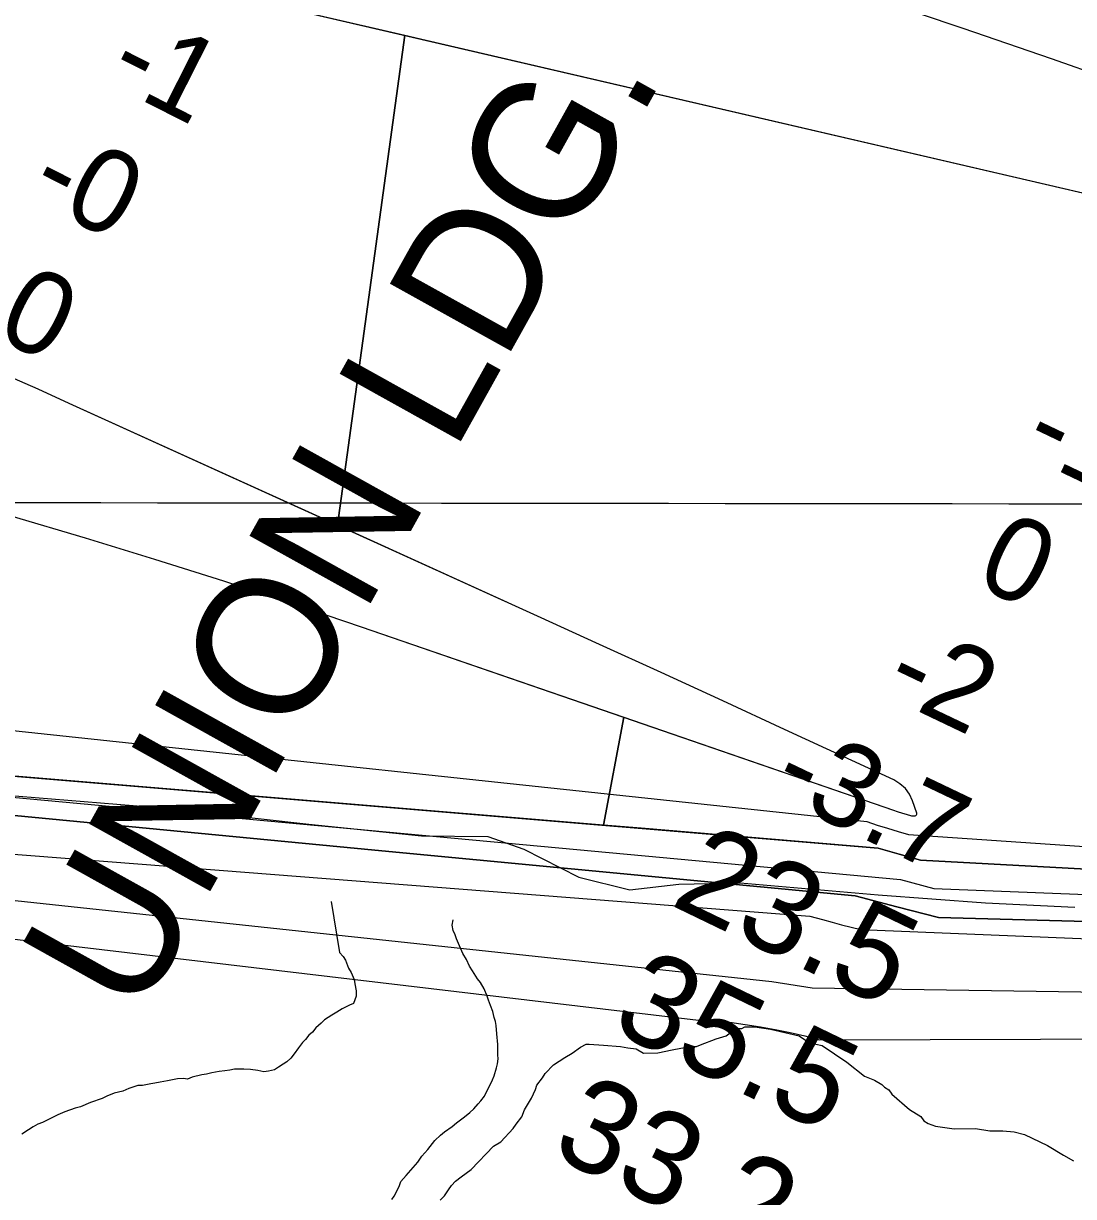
# Model space of a CAD drawing. Extents: x 3219052 to 3256913, y 800770 to 826146.
# Drawn here: x 3237861 to 3238618, y 811725 to 812571 of the extents above; entities that cross this region are included whole.
import ezdxf

# ---------------------------------------------------------------- set-up
doc = ezdxf.new("R2010")
doc.units = 0
for name, color, linetype in [('V-GRID-MAJR', 7, 'Continuous'), ('V-RIVR-EDGE', 7, 'Continuous'), ('V-RIVR-RANG', 7, 'Continuous'), ('V-SITE-VEGE', 7, 'Continuous'), ('V-TOPO-DPTH', 7, 'Continuous'), ('V-TOPO-GNAM-IDEN', 7, 'Continuous'), ('V-TOPO-MAJR', 7, 'Continuous'), ('V-TOPO-MINR', 7, 'Continuous'), ('V-TOPO-SHOR', 7, 'Continuous'), ('V-TOPO-WATR', 7, 'Continuous')]:
    doc.layers.add(name, color=color, linetype=linetype)

msp = doc.modelspace()

# ---------------------------------------------------------------- linework, layer by layer
at = {"layer": 'V-GRID-MAJR'}
msp.add_spline([(3223229.222, 812245.659), (3228465.955, 812237.661), (3233702.6890000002, 812230.425), (3238939.4250000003, 812223.951), (3244176.161, 812218.238), (3249412.899, 812213.287), (3254649.637, 812209.098), (3254649.6380000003, 812209.098)], degree=3, dxfattribs=at)
at = {"layer": 'V-RIVR-EDGE'}
msp.add_lwpolyline([(3237845.700200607, 812014.2978782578), (3237963.4749681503, 812004.8783922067), (3238066.465359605, 811993.322067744), (3238147.7294484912, 811984.8622204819), (3238195.5427916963, 811984.3093126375), (3238221.6008119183, 811975.1166157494), (3238261.106933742, 811955.0236859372), (3238298.031867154, 811945.804118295), (3238333.25141419, 811950.0638223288), (3238377.5905696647, 811950.8235427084), (3238477.1110727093, 811942.3185525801), (3238554.469521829, 811936.4764379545), (3238618.794124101, 811933.2746273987)], dxfattribs=at)
at = {"layer": 'V-SITE-VEGE'}
for points in [[(3238360.298, 811838.404), (3238367.481, 811840.603), (3238371.546, 811843.778), (3238375.634, 811845.9180000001), (3238378.728, 811845.9770000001), (3238380.772, 811847.046), (3238387.992, 811847.186), (3238399.376, 811845.336), (3238420.102, 811840.573), (3238427.424, 811835.5530000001), (3238436.7460000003, 811833.669), (3238454.515, 811821.623), (3238467.089, 811811.542), (3238474.3680000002, 811808.585), (3238479.5840000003, 811805.589), (3238481.688, 811803.5650000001), (3238484.821, 811801.56), (3238486.943, 811798.507), (3238499.536, 811787.394), (3238507.886, 811782.393), (3238510.007, 811779.34), (3238513.1410000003, 811777.335), (3238518.339, 811775.37), (3238531.786, 811773.562), (3238547.256, 811773.857), (3238557.611, 811771.9890000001), (3238566.895, 811772.165), (3238575.166, 811771.291), (3238582.427, 811769.366), (3238599.085, 811761.4280000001), (3238610.5700000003, 811754.424), (3238617.867, 811750.434)], [(3238161.3000000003, 811722.149), (3238164.336, 811725.3030000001), (3238167.352, 811729.487), (3238169.355, 811732.621), (3238172.392, 811735.774), (3238176.46, 811738.947), (3238183.5810000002, 811744.243), (3238199.77, 811761.059), (3238204.87, 811764.252), (3238213.975, 811773.712), (3238215.98, 811776.845), (3238220.008, 811782.082), (3238221.972, 811787.278), (3238226.974, 811795.627), (3238229.949, 811801.876), (3238230.92, 811804.9890000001), (3238234.951, 811810.223), (3238236.954, 811813.361), (3238243.026, 811819.665), (3238251.179, 811824.979), (3238256.279, 811828.172), (3238262.3880000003, 811832.4130000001), (3238266.4760000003, 811834.556), (3238268.538, 811834.595), (3238278.872, 811833.761), (3238291.269, 811832.964), (3238296.446, 811832.03), (3238302.6550000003, 811831.117), (3238307.872, 811828.1190000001), (3238318.185, 811828.3150000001), (3238328.46, 811830.574), (3238334.631, 811831.723), (3238341.832, 811832.8910000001), (3238345.9560000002, 811832.973), (3238349.032, 811834.062), (3238360.298, 811838.404)]]:
    msp.add_lwpolyline(points, dxfattribs=at)
at = {"layer": 'V-TOPO-DPTH'}
for points in [[(3238681.181071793, 812517.4234874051), (3238601.907386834, 812545.1668010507), (3238538.268799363, 812567.1180725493), (3238474.5027999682, 812588.6870187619), (3238410.545682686, 812609.6824770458), (3238346.4611534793, 812630.295610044), (3238054.0245241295, 812722.9125502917), (3238053.059886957, 812723.0832592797), (3238051.1972660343, 812722.8624435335), (3238048.5419894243, 812721.4004480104), (3238048.264964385, 812721.162598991), (3238048.1245901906, 812721.0453539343), (3237968.7772840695, 812656.8193267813), (3237966.404750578, 812654.3878513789), (3237964.6618460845, 812651.4718143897), (3237964.085610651, 812648.3539511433), (3237965.0067713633, 812645.3200458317), (3237977.105712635, 812624.8371600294), (3237984.90913081, 812614.0776569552), (3237993.786760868, 812604.5197553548), (3238004.2757087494, 812596.7642559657), (3238015.8388685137, 812590.2103580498), (3238800.1439429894, 812407.8218294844)], [(3238681.181071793, 812517.4234874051), (3238601.907386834, 812545.1668010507), (3238538.268799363, 812567.1180725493), (3238474.5027999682, 812588.6870187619), (3238410.545682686, 812609.6824770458), (3238346.4611534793, 812630.295610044), (3238054.0245241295, 812722.9125502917), (3238053.059886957, 812723.0832592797), (3238051.1972660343, 812722.8624435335), (3238048.5419894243, 812721.4004480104), (3238048.264964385, 812721.162598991), (3238048.1245901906, 812721.0453539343), (3237968.7772840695, 812656.8193267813), (3237966.404750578, 812654.3878513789), (3237964.6618460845, 812651.4718143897), (3237964.085610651, 812648.3539511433), (3237965.0067713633, 812645.3200458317), (3237977.105712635, 812624.8371600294), (3237984.90913081, 812614.0776569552), (3237993.786760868, 812604.5197553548), (3238004.2757087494, 812596.7642559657), (3238015.8388685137, 812590.2103580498), (3238135.8415661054, 812562.3039780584), (3238087.088944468, 812208.8483856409)], [(3238320.5143739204, 812102.5461848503), (3238275.991739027, 812122.9051701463), (3238231.4442780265, 812143.2099945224), (3238103.1016457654, 812201.5674080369), (3238087.088944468, 812208.8483856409), (3238135.8415661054, 812562.3039780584), (3238151.082310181, 812558.7597744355)], [(3238151.082310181, 812558.7597744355), (3238800.1439429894, 812407.8218294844), (3238805.0494680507, 812407.4696608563), (3238809.8531523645, 812407.7521796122)], [(3238320.5143739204, 812102.5461848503), (3238275.991739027, 812122.9051701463), (3238231.4442780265, 812143.2099945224), (3237893.7614052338, 812296.7544457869), (3237871.2860702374, 812306.889872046), (3237848.769443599, 812316.9319345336)], [(3238087.088944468, 812208.8483856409), (3237893.7614052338, 812296.7544457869), (3237871.2860702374, 812306.889872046), (3237848.769443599, 812316.9319345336)], [(3237851.6740228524, 812215.6477515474), (3237905.268645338, 812199.6485995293), (3237955.2658458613, 812184.378960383), (3238005.1283607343, 812168.6905035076), (3238054.7888471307, 812152.3738200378), (3238104.3146478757, 812135.6383188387), (3238487.9833535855, 812003.2866509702), (3238490.6115121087, 812002.4256119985), (3238491.4929302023, 812002.1552417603), (3238500.259794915, 811999.52442819), (3238501.101298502, 811999.3271251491), (3238503.6690818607, 811999.2202945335), (3238504.274176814, 811999.4867889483), (3238504.7023597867, 811999.8660077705), (3238504.865174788, 812000.4143132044), (3238504.851077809, 812001.0753430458), (3238501.874597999, 812009.9799408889), (3238499.5668234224, 812014.7749039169), (3238496.629291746, 812019.0059783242), (3238492.747124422, 812022.3912197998), (3238488.2351999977, 812025.2125726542), (3238409.4603392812, 812061.6115705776), (3238364.999769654, 812082.1059581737), (3238320.5143739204, 812102.5461848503)], [(3237851.6740228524, 812215.6477515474), (3237905.268645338, 812199.6485995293), (3237955.2658458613, 812184.378960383), (3238005.1283607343, 812168.6905035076), (3238054.7888471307, 812152.3738200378), (3238104.3146478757, 812135.6383188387), (3238293.5981568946, 812070.3424327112), (3238279.0662157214, 811992.5104605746)], [(3238279.0662157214, 811992.5104605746), (3236263.3109329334, 812160.2666766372)], [(3236263.3109329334, 812160.2666766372), (3238476.978607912, 811976.0396943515), (3238492.181669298, 811971.6285749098), (3238507.4172200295, 811967.3272036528), (3239341.521306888, 811922.0926631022)], [(3238306.2032246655, 811990.252050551), (3238279.0662157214, 811992.5104605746), (3238293.5981568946, 812070.3424327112), (3238307.5372550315, 812065.5339537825), (3238487.9833535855, 812003.2866509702), (3238490.6115121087, 812002.4256119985), (3238491.4929302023, 812002.1552417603), (3238500.259794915, 811999.52442819), (3238501.101298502, 811999.3271251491), (3238503.6690818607, 811999.2202945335), (3238504.274176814, 811999.4867889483), (3238504.7023597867, 811999.8660077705), (3238504.865174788, 812000.4143132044), (3238504.851077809, 812001.0753430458), (3238501.874597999, 812009.9799408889), (3238499.5668234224, 812014.7749039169), (3238496.629291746, 812019.0059783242), (3238492.747124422, 812022.3912197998), (3238488.2351999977, 812025.2125726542), (3238409.4603392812, 812061.6115705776), (3238364.999769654, 812082.1059581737), (3238320.5143739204, 812102.5461848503)], [(3239312.1153528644, 811904.4490034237), (3238520.5956911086, 811925.9982919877), (3238490.5360639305, 811933.7220217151), (3238460.533346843, 811941.6564453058), (3238119.1909138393, 811974.039931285), (3237711.6959470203, 812013.2851889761), (3236978.4446943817, 812069.2369252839)], [(3239341.521306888, 811922.0926631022), (3238507.4172200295, 811967.3272036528), (3238492.181669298, 811971.6285749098), (3238476.978607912, 811976.0396943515), (3238306.2032246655, 811990.252050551)]]:
    msp.add_lwpolyline(points, dxfattribs=at)
at = {"layer": 'V-TOPO-MAJR'}
msp.add_lwpolyline([(3236976.675069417, 812003.5082032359), (3237637.9890776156, 811937.6883757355), (3237647.1975861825, 811934.9098504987), (3238351.6437120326, 811851.516588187), (3238356.5495229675, 811852.3458410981), (3238359.097209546, 811852.1997481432), (3238392.1202804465, 811846.9973430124), (3238402.8611950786, 811845.1131436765), (3238413.5483847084, 811842.9820019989), (3238424.154986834, 811840.4804468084), (3238434.7078639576, 811837.7319492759), (3239311.6855875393, 811840.4262749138)], dxfattribs=at)
at = {"layer": 'V-TOPO-MINR'}
for points in [[(3238681.181071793, 812517.4234874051), (3238601.907386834, 812545.1668010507), (3238538.268799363, 812567.1180725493), (3238474.5027999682, 812588.6870187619), (3238410.545682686, 812609.6824770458), (3238346.4611534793, 812630.295610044), (3238054.0245241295, 812722.9125502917), (3238053.059886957, 812723.0832592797), (3238051.1972660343, 812722.8624435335), (3238048.5419894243, 812721.4004480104), (3238048.264964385, 812721.162598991), (3238048.1245901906, 812721.0453539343), (3237968.7772840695, 812656.8193267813), (3237966.404750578, 812654.3878513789), (3237964.6618460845, 812651.4718143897), (3237964.085610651, 812648.3539511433), (3237965.0067713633, 812645.3200458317), (3237977.105712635, 812624.8371600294), (3237984.90913081, 812614.0776569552), (3237993.786760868, 812604.5197553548), (3238004.2757087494, 812596.7642559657), (3238015.8388685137, 812590.2103580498), (3238800.1439429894, 812407.8218294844)], [(3238320.5143739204, 812102.5461848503), (3238275.991739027, 812122.9051701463), (3238231.4442780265, 812143.2099945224), (3237893.7614052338, 812296.7544457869), (3237871.2860702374, 812306.889872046), (3237848.769443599, 812316.9319345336)], [(3237851.6740228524, 812215.6477515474), (3237905.268645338, 812199.6485995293), (3237955.2658458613, 812184.378960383), (3238005.1283607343, 812168.6905035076), (3238054.7888471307, 812152.3738200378), (3238104.3146478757, 812135.6383188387), (3238487.9833535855, 812003.2866509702), (3238490.6115121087, 812002.4256119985), (3238491.4929302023, 812002.1552417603), (3238500.259794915, 811999.52442819), (3238501.101298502, 811999.3271251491), (3238503.6690818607, 811999.2202945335), (3238504.274176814, 811999.4867889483), (3238504.7023597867, 811999.8660077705), (3238504.865174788, 812000.4143132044), (3238504.851077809, 812001.0753430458), (3238501.874597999, 812009.9799408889), (3238499.5668234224, 812014.7749039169), (3238496.629291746, 812019.0059783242), (3238492.747124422, 812022.3912197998), (3238488.2351999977, 812025.2125726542), (3238409.4603392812, 812061.6115705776), (3238364.999769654, 812082.1059581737), (3238320.5143739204, 812102.5461848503)], [(3237070.4625623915, 812144.2142284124), (3238468.788826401, 811995.0523872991), (3238476.280380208, 811992.6359333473), (3238483.788910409, 811990.274512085), (3238491.3229052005, 811987.9956398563), (3238498.873876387, 811985.7718003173), (3239351.2416748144, 811927.6004964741)], [(3237025.2740428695, 812089.4185243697), (3238493.201968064, 811953.2482152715), (3238517.201058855, 811946.7728898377), (3239329.4793078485, 811914.9830428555), (3239338.858920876, 811912.7954531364), (3239348.2552308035, 811910.6843577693), (3239357.676586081, 811908.6880039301), (3239367.114638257, 811906.7681444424), (3239471.7874726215, 811886.1397889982), (3239533.6872031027, 811874.678702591), (3239595.737061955, 811864.1705298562), (3239658.0121133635, 811855.0917276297), (3239720.437293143, 811846.9658390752), (3240170.7075255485, 811793.6118011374), (3240175.304957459, 811793.1094056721), (3240179.907297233, 811792.6628783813), (3240184.516998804, 811792.3001533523), (3240189.13160824, 811791.9932964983), (3240238.2444342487, 811789.1759900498), (3240267.426285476, 811787.77521553), (3240296.6176557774, 811786.7378840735), (3240325.82330469, 811786.2457172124), (3240355.0384726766, 811786.1169934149), (3240791.40437533, 811788.2684641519)], [(3236978.4446943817, 812069.2369252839), (3237711.6959470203, 812013.2851889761), (3238119.1909138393, 811974.039931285), (3238460.533346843, 811941.6564453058), (3238490.5360639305, 811933.7220217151), (3238520.5956911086, 811925.9982919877), (3239312.1153528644, 811904.4490034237)], [(3236942.230676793, 812058.3951681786), (3237652.881814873, 811987.293061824), (3238427.650480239, 811926.8786856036), (3238432.2480299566, 811925.6817593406), (3238436.851338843, 811924.4157481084), (3238443.7453417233, 811922.5580999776), (3238450.6515960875, 811920.7482088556), (3238457.576227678, 811919.009953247), (3238464.5131107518, 811917.3194546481), (3239339.5213585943, 811881.3794800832)], [(3236943.0259246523, 812035.7495556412), (3238400.420479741, 811879.8452404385), (3238429.331135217, 811875.239076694), (3239333.6498527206, 811861.6271375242), (3239361.4474915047, 811857.0846881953), (3239389.268618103, 811852.682627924), (3239803.3859657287, 811788.7659327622), (3239864.9200130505, 811779.8268367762), (3239926.5447105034, 811771.6176601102), (3239988.3053831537, 811764.5033624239), (3240050.156705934, 811758.118984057), (3240118.536101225, 811751.673519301), (3240146.281664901, 811749.3061256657), (3240174.0484149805, 811747.2670447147), (3240201.846944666, 811745.7204327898), (3240229.6666607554, 811744.5021335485), (3240678.498516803, 811728.8310884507)]]:
    msp.add_lwpolyline(points, dxfattribs=at)
at = {"layer": 'V-TOPO-SHOR'}
for points in [[(3238082.737, 811937.5430000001), (3238088.588, 811900.735), (3238091.222, 811897.779), (3238092.985, 811895.236), (3238095.2460000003, 811889.27), (3238097.02, 811886.296), (3238099.265, 811881.189), (3238099.75, 811878.192), (3238100.7060000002, 811873.058), (3238100.7800000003, 811869.196), (3238098.732, 811864.006), (3238095.752, 811862.66), (3238090.651, 811859.988), (3238086.829, 811857.77), (3238083.007, 811855.55), (3238080.466, 811853.784), (3238077.9220000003, 811852.019), (3238075.389, 811849.823), (3238071.592, 811846.317), (3238069.075, 811843.264), (3238066.54, 811841.068), (3238064.023, 811838.017), (3238061.917, 811835.829), (3238058.986, 811831.91), (3238056.0640000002, 811827.562), (3238053.5470000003, 811824.508), (3238050.592, 811821.8740000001), (3238048.048, 811820.109), (3238044.657, 811817.899), (3238041.685, 811816.126), (3238037.409, 811815.186), (3238033.985, 811814.6900000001), (3238029.676, 811815.466), (3238024.508, 811816.228), (3238019.782, 811816.566), (3238012.915, 811816.437), (3238009.488, 811815.941), (3238006.0640000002, 811815.448), (3238001.7800000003, 811814.938), (3237996.645, 811813.981), (3237992.799, 811813.05), (3237989.375, 811812.556), (3237982.541, 811810.707), (3237979.133, 811809.355), (3237976.12, 811809.728), (3237971.828, 811809.6460000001), (3237964.557, 811808.218), (3237959.423, 811807.264), (3237955.577, 811806.3300000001), (3237952.5810000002, 811805.845), (3237946.588, 811804.872), (3237943.156, 811804.806), (3237936.7600000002, 811802.539), (3237932.5, 811800.7390000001), (3237926.088, 811799.3300000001), (3237920.978, 811797.087), (3237917.578, 811795.306), (3237909.042, 811792.568), (3237901.805, 811789.424), (3237897.958, 811788.492), (3237890.713, 811785.778), (3237885.603, 811783.536), (3237881.773, 811781.7440000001), (3237874.542, 811778.172), (3237871.134, 811776.8200000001), (3237867.734, 811775.039), (3237864.34, 811772.827), (3237859.6750000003, 811769.732)], [(3238195.228, 811869.273), (3238192.985, 811874.383), (3238190.321, 811879.055), (3238188.125, 811881.59), (3238184.578, 811887.533), (3238182.366, 811890.925), (3238180.132, 811895.604), (3238177.474, 811899.848), (3238175.223, 811905.386), (3238172.978, 811910.495), (3238172.063, 811913.484), (3238170.719, 811916.463), (3238169.787, 811920.309), (3238170.572, 811924.188)], [(3238126.325, 811722.426), (3238127.992, 811725.033), (3238131.723, 811731.973), (3238132.946, 811735.43), (3238136.727, 811739.797), (3238140.0870000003, 811743.725), (3238145.132, 811749.402), (3238148.054, 811753.75), (3238152.254, 811758.552), (3238157.282, 811765.087), (3238161.501, 811769.032), (3238164.465, 811771.234), (3238169.97, 811775.203), (3238172.9250000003, 811777.834), (3238178.852, 811782.242), (3238182.657, 811785.318), (3238185.612, 811787.949), (3238188.551, 811791.441), (3238190.657, 811793.626), (3238193.165, 811797.11), (3238198.955, 811808.81), (3238200.184, 811811.839), (3238201.796, 811817.453), (3238202.596, 811820.4720000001), (3238202.961, 811823.914), (3238202.904, 811826.919), (3238202.764, 811834.214), (3238202.1890000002, 811841.93), (3238201.644, 811847.929), (3238201.159, 811850.925), (3238200.2430000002, 811853.9130000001), (3238199.303, 811858.1900000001), (3238197.505, 811862.449), (3238196.143, 811866.287), (3238195.228, 811869.273)]]:
    msp.add_lwpolyline(points, dxfattribs=at)
at = {"layer": 'V-TOPO-WATR'}
msp.add_lwpolyline([(3236263.3109329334, 812160.2666766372), (3238476.978607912, 811976.0396943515), (3238492.181669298, 811971.6285749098), (3238507.4172200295, 811967.3272036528), (3239341.521306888, 811922.0926631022)], dxfattribs=at)

# ---------------------------------------------------------------- texts
at = {"layer": 'V-RIVR-RANG'}
for s, height, rotation, p in [('-1', 60, 333.15536111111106, (3237919.1924394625, 812528.9118514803)), ('-0', 60, 333.15536111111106, (3237862.668655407, 812445.4424131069)), ('0', 60, 333.15536111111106, (3237839.0240555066, 812345.3323387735)), ('-1', 60, 334.46927777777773, (3238579.0614385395, 812261.2788896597)), ('0', 60, 334.46927777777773, (3238545.1772392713, 812166.6422565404)), ('-2', 60, 334.46927777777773, (3238479.1067011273, 812087.3789098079)), ('-3.7', 60, 334.46927777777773, (3238397.9011890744, 812015.3440619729)), ('23.5', 67.00000000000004, 334.22832571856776, (3238326.0415960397, 811935.5205512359)), ('35.5', 67.00000000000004, 334.22832571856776, (3238282.77859604, 811845.3635512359)), ('33.2', 67.00000000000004, 334.22832571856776, (3238239.51559604, 811755.206551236))]:
    msp.add_text(s, height=height, rotation=rotation, dxfattribs=at).set_placement(p)
at = {"layer": 'V-TOPO-GNAM-IDEN'}
msp.add_text('UNION LDG.', height=99.99980199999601, rotation=60.89485288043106, dxfattribs=at).set_placement((3237943.1785605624, 811850.9261882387))

doc.saveas('drawing.dxf')
